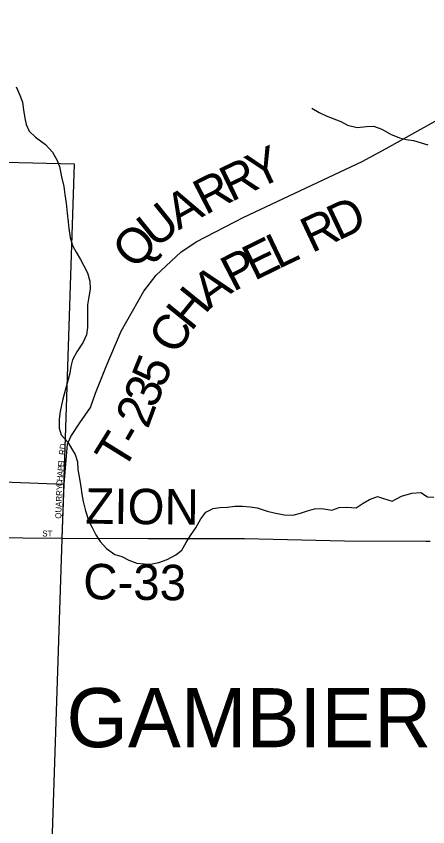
# Model space of a CAD drawing. Extents: x 1759416 to 2214760, y 252598 to 1116833.
# Drawn here: x 1999329 to 2002809, y 862970 to 869830 of the extents above; entities that cross this region are included whole.
import ezdxf

# ---------------------------------------------------------------- set-up
doc = ezdxf.new("R2010")
doc.units = 0
for name, color, linetype in [('GM_X_City_Street', 7, 'Continuous'), ('GM_X_City_Street_Text', 7, 'Continuous'), ('GM_X_Corporation', 7, 'Continuous'), ('GM_X_Corporation_Text', 7, 'Continuous'), ('GM_X_County_Road', 7, 'Continuous'), ('GM_X_County_Road_Text', 7, 'Continuous'), ('GM_X_Minor_River', 7, 'Continuous'), ('GM_X_Township_Road', 7, 'Continuous'), ('GM_X_Township_Road_Text', 7, 'Continuous')]:
    doc.layers.add(name, color=color, linetype=linetype)

msp = doc.modelspace()

# ---------------------------------------------------------------- linework, layer by layer
at = {"layer": 'GM_X_City_Street'}
for points in [[(1999717.3, 865412.9), (1999735.1, 865868.5), (1999764.2, 866209.2)], [(1996706.9, 865983.2), (1996712.5, 865983), (1997188.1, 865974.7), (1997237.5, 865972.4), (1997493.7, 865960.5), (1997712, 865953.5), (1998437.4, 865930.1), (1999070.4, 865894.6), (1999735.1, 865868.5)], [(1998686.6, 865422.4), (1998703.5, 865421.7), (1999050.8, 865418.2), (1999717.3, 865412.9)]]:
    msp.add_lwpolyline(points, dxfattribs=at)
at = {"layer": 'GM_X_Corporation'}
msp.add_lwpolyline([(1995164.1, 866739.8), (1995314.2, 866681.7), (1995383.4, 868686.5), (1999819.1, 868581.1), (1999588.4, 861541.7), (1998095.9, 861586.6), (1998095.9, 861869.1), (1996672.1, 863061), (1996252.2, 863419.1), (1996024, 863689.3), (1996049.1, 863823.2), (1996026.8, 864096.1), (1995996.4, 864335.7), (1995922.2, 864777.7), (1995787.5, 865191.2), (1995555, 865431.3), (1995273.4, 865523.6), (1995302.8, 866417.6), (1995266.6, 866387.2), (1995255, 866343.7), (1995148.7, 866372.2), (1995082.4, 866514.5)], close=True, dxfattribs=at)
at = {"layer": 'GM_X_County_Road'}
for points in [[(1999717.3, 865412.9), (2000443.7, 865410.3)], [(2000443.7, 865410.3), (2000488.8, 865410.2), (2001258.2, 865410.8), (2002105.7, 865390.8), (2002792.3, 865387.7), (2002830.1, 865387.5)]]:
    msp.add_lwpolyline(points, dxfattribs=at)
at = {"layer": 'GM_X_Minor_River'}
for points in [[(1999328.3, 869231.4), (1999359.9, 869163.1), (1999381.5, 869102.9), (1999391.1, 869038.7), (1999402.7, 868966.5), (1999412.4, 868914.4), (1999438, 868858.1), (1999491.8, 868807.7), (1999577.4, 868743.1), (1999635.1, 868678.6), (1999676.7, 868610.2), (1999694.4, 868558), (1999711.8, 868471.8), (1999731.3, 868387.5), (1999738.9, 868321.4), (1999750.4, 868247.2), (1999759.9, 868163), (1999767.5, 868090.8), (1999775.1, 868032.7), (1999784.6, 867956.5), (1999804.2, 867890.3), (1999835.9, 867834), (1999873.5, 867769.7), (1999901.2, 867717.4), (1999932.9, 867659.1), (1999950.4, 867588.9), (1999954, 867518.7), (1999941.5, 867438.7), (1999931.2, 867388.7), (1999930.7, 867322.6), (1999932.3, 867256.5), (1999931.9, 867194.4), (1999923.5, 867132.3), (1999895.1, 867072.4), (1999842.5, 866990.6), (1999804.1, 866922.8), (1999791.7, 866864.7), (1999781.3, 866808.7), (1999769, 866754.7), (1999752.6, 866694.7), (1999734.2, 866632.8), (1999719.8, 866578.8), (1999701.2, 866484.7), (1999692.8, 866418.7), (1999692.3, 866342.5), (1999710, 866288.3), (1999765.6, 866223.9), (1999797.3, 866171.6), (1999829, 866121.3), (1999846.6, 866059.1), (1999850.2, 865993), (1999867.7, 865900.7), (1999875.3, 865846.6), (1999882.9, 865786.5), (1999894.5, 865722.3), (1999914.1, 865644), (1999943.5, 865555.7), (1999971.2, 865503.4), (2000002.9, 865441.2), (2000038.5, 865384.8), (2000092.2, 865324.4), (2000163.9, 865273.9), (2000221.9, 865257.5), (2000281.8, 865227), (2000347.7, 865200.6), (2000413.7, 865194.2), (2000463.7, 865193.8), (2000535.9, 865207.4), (2000604.1, 865231), (2000678.4, 865270.6), (2000728.7, 865310.3), (2000767.2, 865376.2), (2000803.6, 865436), (2000848, 865499.9), (2000890.5, 865575.7), (2000930.9, 865631.5), (2000993.2, 865663.2), (2001051.3, 865672.8), (2001115.4, 865676.4), (2001177.5, 865684), (2001241.6, 865683.6), (2001307.6, 865677.2), (2001367.6, 865668.8)], [(2001827.5, 869053.2), (2001891.3, 869014.7), (2001949.2, 868988.3), (2002073, 868939.5), (2002130.9, 868907), (2002212.8, 868888.5), (2002291, 868898), (2002351, 868899.6), (2002420.9, 868873.1), (2002494.7, 868830.6), (2002570.6, 868802.1), (2002626.6, 868787.7), (2002688.6, 868777.3), (2002810.4, 868740.4)], [(2001367.6, 865668.8), (2001451.5, 865642.2), (2001509.5, 865627.8), (2001593.4, 865611.3), (2001667.5, 865608.8), (2001731.6, 865624.4), (2001791.8, 865644.1), (2001850, 865659.7), (2001914.1, 865663.3), (2001998, 865648.8), (2002058.3, 865672.4), (2002124.3, 865674), (2002202.4, 865669.5), (2002262.7, 865709.2), (2002314.9, 865738.9), (2002383.1, 865764.5), (2002435.1, 865748.1), (2002509, 865725.6), (2002585.4, 865767.2), (2002673.6, 865794.7), (2002749.7, 865798.2), (2002807.5, 865763.8), (2002859.6, 865759.4)]]:
    msp.add_lwpolyline(points, dxfattribs=at)
at = {"layer": 'GM_X_Township_Road'}
msp.add_lwpolyline([(1999764.2, 866209.2), (1999791.8, 866272.9), (1999868.4, 866387.8), (1999957, 866519), (2000000, 866640.8), (2000088.3, 866865.3), (2000216, 867165), (2000407, 867504.1), (2000511.2, 867638.4), (2000722.3, 867833.5), (2000850.9, 867920.9), (2001252.3, 868129), (2002253.4, 868600), (2002458.2, 868711.1), (2003259.1, 869159.2), (2004303.5, 869745.5), (2004391.6, 869785.5), (2004463.7, 869801.4), (2004630.6, 869830)], dxfattribs=at)

# ---------------------------------------------------------------- texts
at = {"layer": 'GM_X_City_Street_Text'}
for s, rotation, p in [('RD', 83.99458, (1999740.1, 866114.6)), ('E', 84.40364, (1999732.2, 866014.1)), ('L', 84.41373, (1999735.7, 866049.2)), ('P', 84.38999, (1999728.8, 865979.1)), ('H', 84.46122, (1999720.3, 865891.5)), ('A', 84.41771, (1999724.5, 865935.3)), ('QUARRY', 88.05951, (1999709.1, 865576.7)), ('C', 86.37973, (1999717.8, 865852.4)), ('ST', 0.00001, (1999549.9, 865427.1))]:
    msp.add_text(s, height=50, rotation=rotation, dxfattribs=at).set_placement(p)
at = {"layer": 'GM_X_Corporation_Text'}
msp.add_text('GAMBIER', height=500, rotation=0.00001, dxfattribs=at).set_placement((1999754.2, 863643.6))
at = {"layer": 'GM_X_County_Road_Text'}
for s, rotation, p in [('ZION', 359.42651, (1999912.9, 865535.7)), ('C-33', 359.31241, (1999894.3, 864896.5))]:
    msp.add_text(s, height=300, rotation=rotation, dxfattribs=at).set_placement(p)
at = {"layer": 'GM_X_Township_Road_Text'}
for s, rotation, p in [('Y', 25.2682, (2001367.7, 868362.1)), ('R', 25.76387, (2001146.4, 868255.3)), ('R', 27.05377, (2000928.6, 868144)), ('A', 29.26548, (2000701, 868016.4)), ('U', 38.82934, (2000506.2, 867858.2)), ('D', 25.24048, (2002050.7, 867928)), ('R', 25.28027, (2001827.9, 867822.8)), ('Q', 45.99948, (2000330.2, 867675)), ('L', 25.56265, (2001542.3, 867686.6)), ('E', 26.31206, (2001342.1, 867587.6)), ('P', 27.4257, (2001163.8, 867495)), ('A', 35.87391, (2000959.9, 867346.5)), ('H', 51.00509, (2000808.9, 867155.7)), ('C', 59.9051, (2000692.3, 866952.6)), ('5', 67.84489, (2000574, 866673)), ('3', 68.20438, (2000505.6, 866501.8)), ('2', 69.71463, (2000442.3, 866330.5)), ('T', 58.24537, (2000234, 865974.2)), ('-', 60.04759, (2000357.4, 866173.8))]:
    msp.add_text(s, height=300, rotation=rotation, dxfattribs=at).set_placement(p)

doc.saveas('drawing.dxf')
